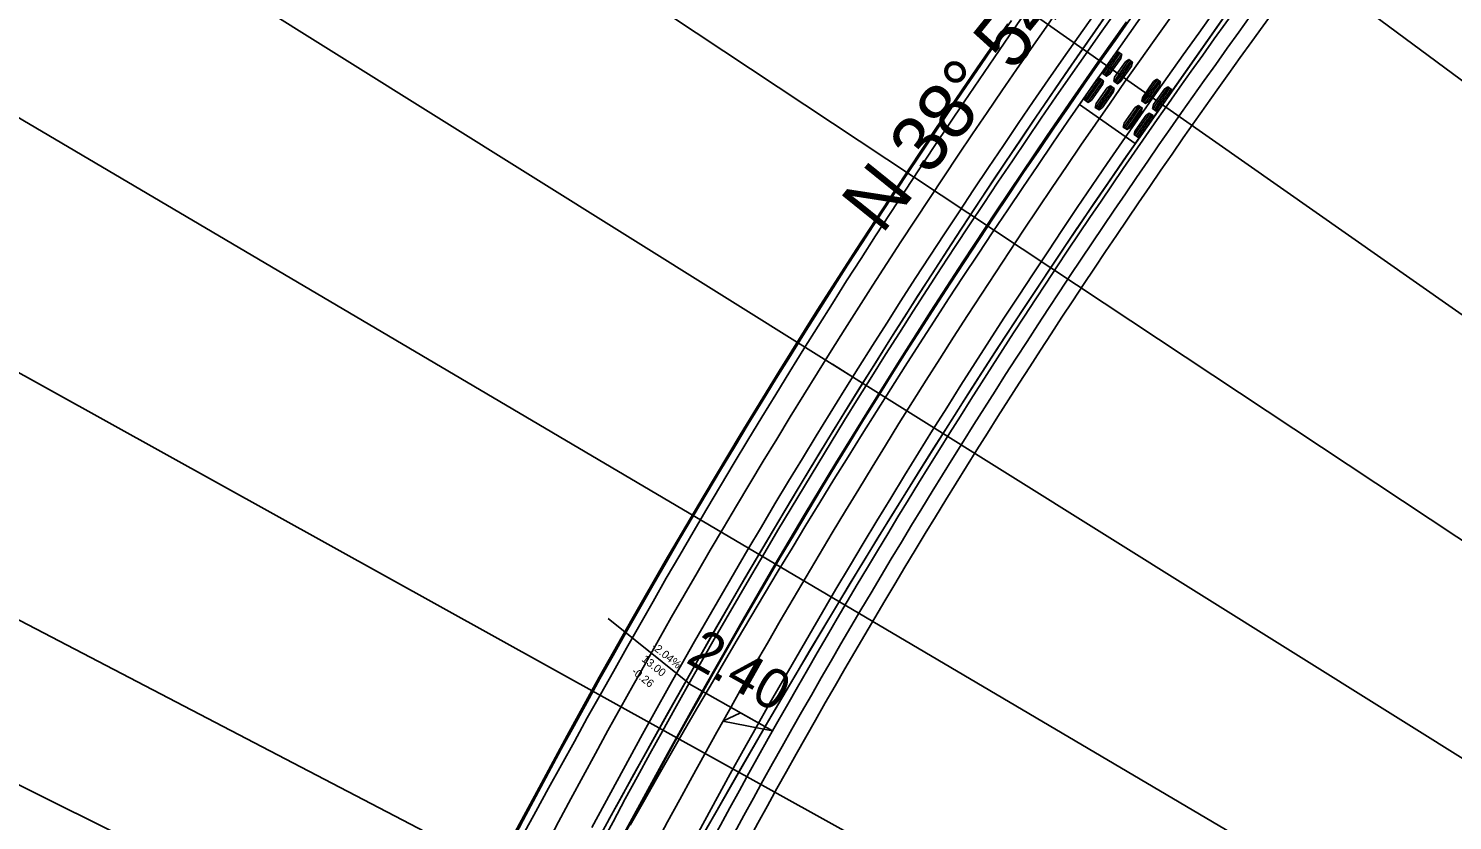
# Model space of a CAD drawing. Extents: x 2293233 to 2294507, y 892788 to 894229.
# Drawn here: x 2294121.5 to 2294299.4, y 893908.4 to 894007.4 of the extents above; entities that cross this region are included whole.
import ezdxf

# ---------------------------------------------------------------- set-up
doc = ezdxf.new("R2010")
doc.units = 0
for name, color, linetype in [('COGO Default Curve', 7, 'Continuous'), ('Default', 7, 'Continuous'), ('Prop EOT', 7, 'Continuous'), ('Prop Horizontal Alignment', 7, 'Continuous'), ('Prop Paved Shoulder', 7, 'Continuous'), ('Prop Superelevation  Arrow CELL', 7, 'Continuous'), ('Prop Superelevation Label', 7, 'Continuous'), ('Scratch_Level_4', 7, 'Continuous'), ('Scratch_Level_5', 7, 'Continuous'), ('Scratch_Level_6', 7, 'Continuous')]:
    doc.layers.add(name, color=color, linetype=linetype)

msp = doc.modelspace()

# ---------------------------------------------------------------- linework, layer by layer
at = {"layer": 'COGO Default Curve'}
for p, q in [((2294283.26, 894041.28), (2294252.82, 893997.89)), ((2294259.78, 893993.01), (2294290.22, 894036.4)), ((2294257.69, 894004.43), (2294255.79, 894001.73)), ((2294257.88, 894004.3), (2294255.98, 894001.6)), ((2294258.06, 894004.17), (2294256.17, 894001.47)), ((2294259.04, 894003.49), (2294257.14, 894000.79)), ((2294259.23, 894003.36), (2294257.33, 894000.65)), ((2294259.41, 894003.22), (2294257.52, 894000.52)), ((2294255.39, 894001.16), (2294253.49, 893998.46)), ((2294255.58, 894001.03), (2294253.68, 893998.33)), ((2294255.77, 894000.9), (2294253.87, 893998.2)), ((2294256.74, 894000.21), (2294254.85, 893997.51)), ((2294256.93, 894000.08), (2294255.03, 893997.38)), ((2294262.54, 894001.03), (2294260.65, 893998.33)), ((2294262.73, 894000.9), (2294260.84, 893998.19)), ((2294262.92, 894000.76), (2294261.02, 893998.06)), ((2294263.9, 894000.08), (2294262, 893997.38)), ((2294257.12, 893999.95), (2294255.22, 893997.25)), ((2294264.08, 893999.95), (2294262.19, 893997.25)), ((2294264.27, 893999.82), (2294262.37, 893997.11)), ((2294252.82, 893997.89), (2294259.78, 893993.01)), ((2294260.25, 893997.75), (2294258.35, 893995.05)), ((2294260.43, 893997.62), (2294258.54, 893994.92)), ((2294260.62, 893997.49), (2294258.73, 893994.79)), ((2294261.6, 893996.8), (2294259.7, 893994.1)), ((2294261.79, 893996.67), (2294259.89, 893993.97)), ((2294261.97, 893996.54), (2294260.08, 893993.84))]:
    msp.add_line(p, q, dxfattribs=at)
for points in [[(2294290.04, 894036.15), (2294259.02, 893991.91), (2294255.81, 893987.24), (2294252.43, 893982.28), (2294249.28, 893977.58), (2294245.96, 893972.58), (2294242.67, 893967.56), (2294239.42, 893962.52), (2294236.19, 893957.46), (2294232.99, 893952.39), (2294229.12, 893946.16), (2294225.29, 893939.91), (2294221.33, 893933.35), (2294217.42, 893926.77), (2294213.54, 893920.16), (2294209.54, 893913.24), (2294205.58, 893906.3)], [(2294256.78, 894009.93), (2294251.82, 894002.81), (2294246.93, 893995.66), (2294242.09, 893988.47), (2294237.32, 893981.23), (2294233.33, 893975.08), (2294229.56, 893969.18), (2294225.66, 893962.97), (2294221.98, 893957.01), (2294218.17, 893950.75), (2294214.57, 893944.74), (2294211.02, 893938.7), (2294207.35, 893932.35), (2294201.43, 893921.91), (2294194.8, 893909.96), (2294162.57, 893850.95), (2294158.86, 893844.23), (2294154.94, 893837.24), (2294150.96, 893830.3), (2294146.92, 893823.38), (2294142.82, 893816.51), (2294137.26, 893807.39), (2294131.61, 893798.35)], [(2294245.94, 894009.25), (2294244.04, 894006.5), (2294242.15, 894003.75), (2294240.27, 894000.99), (2294238.4, 893998.22), (2294236.53, 893995.44), (2294234.67, 893992.66), (2294232.83, 893989.88), (2294230.99, 893987.09), (2294229.16, 893984.29), (2294227.34, 893981.48), (2294225.53, 893978.67), (2294223.73, 893975.86), (2294221.94, 893973.03), (2294220.16, 893970.2), (2294218.39, 893967.37), (2294216.62, 893964.53), (2294214.87, 893961.68), (2294213.13, 893958.83), (2294211.39, 893955.97), (2294209.67, 893953.11), (2294207.95, 893950.24), (2294206.25, 893947.36), (2294204.55, 893944.48), (2294202.87, 893941.59), (2294201.19, 893938.7), (2294199.53, 893935.8), (2294197.87, 893932.89), (2294196.22, 893929.98), (2294194.58, 893927.07), (2294192.95, 893924.16), (2294191.32, 893921.24), (2294189.7, 893918.31), (2294188.09, 893915.39), (2294186.48, 893912.46), (2294184.87, 893909.54), (2294183.27, 893906.61)], [(2294254.65, 894009.15), (2294252.73, 894006.43), (2294250.83, 894003.72), (2294248.93, 894000.99), (2294247.05, 893998.26), (2294245.17, 893995.52), (2294243.31, 893992.77), (2294241.45, 893990.02), (2294239.6, 893987.26), (2294237.77, 893984.5), (2294235.94, 893981.73), (2294234.12, 893978.95), (2294232.31, 893976.17), (2294230.51, 893973.38), (2294228.73, 893970.58), (2294226.95, 893967.78), (2294225.18, 893964.97), (2294223.42, 893962.16), (2294221.67, 893959.34), (2294219.93, 893956.51), (2294218.2, 893953.68), (2294216.48, 893950.84), (2294214.77, 893947.99), (2294213.07, 893945.14), (2294211.38, 893942.29), (2294209.7, 893939.43), (2294208.03, 893936.56), (2294206.37, 893933.68), (2294204.72, 893930.8), (2294203.08, 893927.92), (2294201.45, 893925.03), (2294199.83, 893922.13), (2294198.22, 893919.23), (2294196.62, 893916.32), (2294195.03, 893913.4), (2294193.45, 893910.49), (2294191.88, 893907.56)], [(2294256.72, 894009.85), (2294254.82, 894007.13), (2294252.93, 894004.41), (2294251.04, 894001.68), (2294249.17, 893998.95), (2294247.3, 893996.21), (2294245.44, 893993.46), (2294243.59, 893990.71), (2294241.75, 893987.96), (2294239.92, 893985.19), (2294238.1, 893982.42), (2294236.28, 893979.65), (2294234.48, 893976.87), (2294232.68, 893974.08), (2294230.9, 893971.29), (2294229.12, 893968.49), (2294227.36, 893965.68), (2294225.6, 893962.87), (2294223.85, 893960.06), (2294222.11, 893957.24), (2294220.38, 893954.41), (2294218.67, 893951.58), (2294216.96, 893948.74), (2294215.26, 893945.89), (2294213.57, 893943.04), (2294211.89, 893940.18), (2294210.22, 893937.32), (2294208.55, 893934.45), (2294206.9, 893931.57), (2294205.26, 893928.69), (2294203.62, 893925.8), (2294201.99, 893922.91), (2294200.37, 893920.01), (2294198.75, 893917.11), (2294197.14, 893914.2), (2294195.53, 893911.29), (2294193.93, 893908.37)], [(2294204.41, 893905.52), (2294205.99, 893908.44), (2294207.59, 893911.36), (2294209.19, 893914.27), (2294210.81, 893917.17), (2294212.43, 893920.07), (2294214.06, 893922.96), (2294215.71, 893925.85), (2294217.36, 893928.73), (2294219.03, 893931.6), (2294220.7, 893934.47), (2294222.39, 893937.33), (2294224.08, 893940.18), (2294225.79, 893943.03), (2294227.5, 893945.88), (2294229.23, 893948.71), (2294230.96, 893951.55), (2294232.71, 893954.37), (2294234.46, 893957.19), (2294236.23, 893960), (2294238, 893962.81), (2294239.79, 893965.61), (2294241.58, 893968.4), (2294243.38, 893971.19), (2294245.2, 893973.97), (2294247.02, 893976.74), (2294248.86, 893979.51), (2294250.7, 893982.27), (2294252.55, 893985.03), (2294254.42, 893987.77), (2294256.29, 893990.52), (2294258.17, 893993.25), (2294260.06, 893995.98), (2294261.96, 893998.7), (2294263.88, 894001.41), (2294265.8, 894004.12), (2294267.73, 894006.82), (2294269.67, 894009.52)], [(2294170.85, 893860.96), (2294201.32, 893916.77), (2294206.03, 893925.23), (2294210.82, 893933.63), (2294214.68, 893940.26), (2294218.43, 893946.57), (2294222.39, 893953.14), (2294226.23, 893959.39), (2294230.12, 893965.6), (2294234.24, 893972.07), (2294238.23, 893978.23), (2294242.45, 893984.63), (2294245.61, 893989.33), (2294248.79, 893994.02), (2294252, 893998.69), (2294255.43, 894003.62), (2294258.69, 894008.24)], [(2294244.34, 894008.39), (2294242.43, 894005.65), (2294240.53, 894002.89), (2294238.64, 894000.13), (2294236.75, 893997.36), (2294234.88, 893994.59), (2294233.02, 893991.81), (2294231.17, 893989.02), (2294229.32, 893986.23), (2294227.49, 893983.43), (2294225.67, 893980.62), (2294223.85, 893977.81), (2294222.05, 893974.99), (2294220.25, 893972.16), (2294218.47, 893969.33), (2294216.7, 893966.49), (2294214.93, 893963.65), (2294213.18, 893960.8), (2294211.43, 893957.94), (2294209.7, 893955.08), (2294207.97, 893952.21), (2294206.26, 893949.34), (2294204.55, 893946.46), (2294202.86, 893943.57), (2294201.17, 893940.68), (2294199.5, 893937.78), (2294197.84, 893934.88), (2294196.18, 893931.97), (2294194.54, 893929.05), (2294192.9, 893926.13), (2294191.28, 893923.21), (2294189.67, 893920.27), (2294188.06, 893917.33), (2294186.47, 893914.39), (2294184.89, 893911.44), (2294183.32, 893908.49), (2294181.75, 893905.53)], [(2294182.32, 893907.01), (2294184.99, 893912.02), (2294188.79, 893919.06), (2294192.82, 893926.36), (2294196.91, 893933.62), (2294201.06, 893940.85), (2294205.78, 893948.89), (2294210.41, 893956.61), (2294215.29, 893964.56), (2294220.06, 893972.19), (2294224.91, 893979.77), (2294229.83, 893987.3), (2294234.81, 893994.79), (2294240.06, 894002.5), (2294243.86, 894007.98)], [(2294195.75, 893906.31), (2294197.33, 893909.25), (2294198.93, 893912.19), (2294200.53, 893915.13), (2294202.15, 893918.06), (2294203.77, 893920.98), (2294205.41, 893923.9), (2294207.05, 893926.81), (2294208.71, 893929.72), (2294210.38, 893932.62), (2294212.06, 893935.52), (2294213.74, 893938.41), (2294215.44, 893941.3), (2294217.15, 893944.17), (2294218.87, 893947.05), (2294220.6, 893949.91), (2294222.34, 893952.78), (2294224.08, 893955.63), (2294225.84, 893958.48), (2294227.61, 893961.32), (2294229.39, 893964.16), (2294231.18, 893966.99), (2294232.98, 893969.81), (2294234.79, 893972.63), (2294236.61, 893975.44), (2294238.44, 893978.24), (2294240.28, 893981.04), (2294242.13, 893983.83), (2294243.98, 893986.62), (2294245.85, 893989.4), (2294247.73, 893992.17), (2294249.62, 893994.93), (2294251.52, 893997.69), (2294253.42, 894000.44), (2294255.34, 894003.19), (2294257.27, 894005.92), (2294259.2, 894008.66)], [(2294196.69, 893907.84), (2294198.33, 893910.75), (2294199.98, 893913.65), (2294201.64, 893916.55), (2294203.31, 893919.45), (2294204.98, 893922.34), (2294206.66, 893925.23), (2294208.35, 893928.11), (2294210.04, 893931), (2294211.75, 893933.87), (2294213.46, 893936.74), (2294215.18, 893939.61), (2294216.9, 893942.47), (2294218.64, 893945.33), (2294220.38, 893948.18), (2294222.13, 893951.03), (2294223.9, 893953.87), (2294225.67, 893956.71), (2294227.44, 893959.54), (2294229.23, 893962.36), (2294231.03, 893965.19), (2294232.83, 893968), (2294234.65, 893970.81), (2294236.47, 893973.61), (2294238.3, 893976.41), (2294240.15, 893979.2), (2294242, 893981.98), (2294243.86, 893984.76), (2294245.73, 893987.54), (2294247.6, 893990.3), (2294249.49, 893993.06), (2294251.39, 893995.82), (2294253.3, 893998.56), (2294255.21, 894001.3), (2294255.4, 894001.58)], [(2294205.72, 893906.55), (2294207.37, 893909.44), (2294209.02, 893912.32), (2294210.67, 893915.2), (2294212.33, 893918.08), (2294214, 893920.95), (2294215.68, 893923.81), (2294217.36, 893926.68), (2294219.05, 893929.53), (2294220.75, 893932.38), (2294222.46, 893935.23), (2294224.17, 893938.07), (2294225.9, 893940.91), (2294227.63, 893943.74), (2294229.37, 893946.56), (2294231.11, 893949.38), (2294232.87, 893952.2), (2294234.64, 893955.01), (2294236.41, 893957.81), (2294238.19, 893960.61), (2294239.98, 893963.4), (2294241.78, 893966.19), (2294243.59, 893968.97), (2294245.41, 893971.74), (2294247.23, 893974.51), (2294249.07, 893977.27), (2294250.91, 893980.02), (2294252.77, 893982.77), (2294254.63, 893985.52), (2294256.5, 893988.25), (2294258.38, 893990.98), (2294260.27, 893993.71), (2294262.17, 893996.43), (2294262.36, 893996.7)]]:
    msp.add_lwpolyline(points, dxfattribs=at)
for points in [[(2294257.64, 894004.47), (2294258.11, 894004.14), (2294257.98, 894003.66), (2294256.62, 894001.72), (2294256.21, 894001.44), (2294255.75, 894001.77), (2294255.87, 894002.24), (2294257.23, 894004.19)], [(2294258.99, 894003.52), (2294259.46, 894003.19), (2294259.34, 894002.71), (2294257.97, 894000.77), (2294257.56, 894000.49), (2294257.1, 894000.82), (2294257.22, 894001.3), (2294258.59, 894003.24)], [(2294255.34, 894001.19), (2294255.81, 894000.86), (2294255.69, 894000.39), (2294254.32, 893998.44), (2294253.92, 893998.16), (2294253.45, 893998.49), (2294253.57, 893998.97), (2294254.94, 894000.91)], [(2294256.69, 894000.25), (2294257.16, 893999.92), (2294257.04, 893999.44), (2294255.67, 893997.49), (2294255.27, 893997.22), (2294254.8, 893997.54), (2294254.92, 893998.02), (2294256.29, 893999.97)], [(2294262.5, 894001.06), (2294262.97, 894000.73), (2294262.84, 894000.25), (2294261.48, 893998.31), (2294261.07, 893998.03), (2294260.6, 893998.36), (2294260.73, 893998.84), (2294262.09, 894000.78)], [(2294263.85, 894000.11), (2294264.32, 893999.78), (2294264.19, 893999.31), (2294262.83, 893997.36), (2294262.42, 893997.08), (2294261.95, 893997.41), (2294262.08, 893997.89), (2294263.44, 893999.83)], [(2294260.2, 893997.79), (2294260.67, 893997.46), (2294260.54, 893996.98), (2294259.18, 893995.03), (2294258.77, 893994.76), (2294258.3, 893995.08), (2294258.43, 893995.56), (2294259.79, 893997.51)], [(2294261.55, 893996.84), (2294262.02, 893996.51), (2294261.9, 893996.03), (2294260.53, 893994.09), (2294260.12, 893993.81), (2294259.66, 893994.14), (2294259.78, 893994.61), (2294261.14, 893996.56)]]:
    msp.add_lwpolyline(points, close=True, dxfattribs=at)
for centre in [(2294255.4, 894001.58), (2294262.36, 893996.7)]:
    msp.add_circle(centre, 0.0417, dxfattribs=at)
for radius in [956, 944]:
    msp.add_arc((2295031.56, 893458.96), radius, 141.09608, 153.52096, dxfattribs=at)
at = {"layer": 'Default'}
msp.add_line((2294193.91, 893933.69), (2294204.03, 893925.53), dxfattribs=at)
at = {"layer": 'Prop EOT'}
msp.add_arc((2295031.56, 893458.96), 938, 143.86429, 153.52096, dxfattribs=at)
at = {"layer": 'Prop Horizontal Alignment'}
for p, q in [((2294179.88, 893883.21), (2293935.07, 894005.15)), ((2294226.18, 893962.8), (2294221.94, 893965.46))]:
    msp.add_line(p, q, dxfattribs=at)
msp.add_arc((2295031.56, 893458.96), 950, 141.09608, 153.52096, dxfattribs=at)
msp.add_arc((2295031.56, 893458.96), 950, 141.09608, 153.52096, dxfattribs=at)
at = {"layer": 'Prop Paved Shoulder'}
msp.add_arc((2295031.56, 893458.96), 936, 143.86429, 153.52096, dxfattribs=at)
at = {"layer": 'Prop Superelevation  Arrow CELL'}
msp.add_line((2294214.48, 893919.63), (2294204.03, 893925.52), dxfattribs=at)
msp.add_lwpolyline([(2294214.48, 893919.63), (2294208.27, 893920.83), (2294210.45, 893921.9)], close=True, dxfattribs=at)
at = {"layer": 'Scratch_Level_4'}
for p, q in [((2294147.93, 894114.09), (2294388.92, 893935.42)), ((2294131, 894090.61), (2294376.61, 893918.34)), ((2294114.69, 894066.69), (2294364.75, 893900.95)), ((2294099.01, 894042.36), (2294353.35, 893883.25)), ((2294083.99, 894017.62), (2294342.42, 893865.26)), ((2294069.61, 893992.49), (2294331.96, 893846.98)), ((2294055.91, 893966.99), (2294322, 893828.44))]:
    msp.add_line(p, q, dxfattribs=at)
at = {"layer": 'Scratch_Level_5'}
msp.add_arc((2295031.56, 893458.96), 934, 143.86429, 153.52096, dxfattribs=at)
at = {"layer": 'Scratch_Level_6'}
msp.add_line((2294193.91, 893933.69), (2294204.03, 893925.53), dxfattribs=at)

# ---------------------------------------------------------------- texts
at = {"layer": 'Default'}
for s, p in [('13.00', (2294198.03, 893928.44)), ('-2.04%', (2294199.28, 893930)), ('-0.26', (2294196.77, 893926.89))]:
    msp.add_text(s, height=1, rotation=321.0961, dxfattribs=at).set_placement(p)
at = {"layer": 'Prop Horizontal Alignment'}
msp.add_text('N 38%%d 54\' 14.1" E', height=7, rotation=51.0961, dxfattribs=at).set_placement((2294228.11, 893981.55))
at = {"layer": 'Prop Superelevation Label'}
msp.add_text('2.40', height=5, rotation=330.586, dxfattribs=at).set_placement((2294203.47, 893928.25))

doc.saveas('drawing.dxf')
